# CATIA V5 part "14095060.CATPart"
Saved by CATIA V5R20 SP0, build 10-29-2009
Part number: 14095060
Definition: NONE
Nomenclature: 14095060
Source: Unknown
Description: 14095060
Bounding box of the stored display mesh (mm): x -30 to 120, y -61.5 to 51.6, z -51.6 to 51.6
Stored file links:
  C:\Users\Utente\Desktop\IO LAVORO\3D X SITO CF\X SITO\PLASTICA\RF2\14095060.CATPart
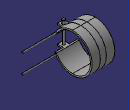
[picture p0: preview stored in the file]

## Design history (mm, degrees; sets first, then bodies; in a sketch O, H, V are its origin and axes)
Body1 "14095060" (main body)
  Solid1: solid without history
